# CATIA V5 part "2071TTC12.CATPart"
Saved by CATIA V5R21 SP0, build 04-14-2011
Part number: 2071TTC12
Bounding box of the stored display mesh (mm): x -10 to 10, y 0 to 1000, z -16 to 14
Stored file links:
  C:\Users\ALI OZGUN\Desktop\alhan\PROFILLER\2071TTC12.CATPart
  Copy (1) of 2070TT001.CATPart
  C:\Users\ALI OZGUN\Desktop\alhan\PROFILLER\2071TTC38.CATPart
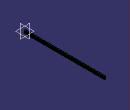
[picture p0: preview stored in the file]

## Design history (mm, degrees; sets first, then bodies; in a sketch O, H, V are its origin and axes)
Body1 (main body)
  Sketch1 on zx-plane, origin (0, 0, 0), H (-1, 0, 0), V (0, 0, 1)
    line L1 (10, 11.8) -> (10, -14)
    line L2 (10, -14) -> (-10, -14)
    line L3 (-10, -14) -> (-10, -1.7)
    line L4 (-10, 14) -> (-2.6, 14)
    point P4 (-10, 2.6)
    line L5 (-2.6, -1.7) -> (-10, -1.7)
    line L6 (-10, 6.9) -> (-2.6, 6.9)
    point P5 (-9.0936, 12.527)
    point P6 (-0.35, 2.6)
    line L7 (1.9, 9.1) -> (1.9, -3.9)
    line L8 (1.9, -3.9) -> (-2.6, -3.9)
    line L9 (-2.6, -3.9) -> (-2.6, -1.7)
    line L10 (-2.6, 9.1) -> (1.9, 9.1)
    line L11 (10, 11.8) -> (-2.6, 11.8)
    line L12 (-2.6, 11.8) -> (-2.6, 14)
    axis line L13 (-44.5224, 2.6) -> (23.1973, 2.6)
    line L14 (-10, 6.9) -> (-10, 14)
    point P18 (-2.6, 6.9)
    line L15 (-2.6, 6.9) -> (-2.6, 9.1)
    distance L6 L5 = 8.6
    distance L10 L8 = 13
    distance L7 L9 = 4.5
    distance L12 L3 = 7.4
    distance L1 L3 = 20
    distance L4 L2 = 28
    distance L11 L4 = 2.2
    distance L13 L4 = 11.4
    vertical: L1 V, L3 V, L7 V, L9 V, L12 V, L14 V, L15 V
    horizontal: L2 H, L4 H, L5 H, L6 H, L8 H, L10 H, L11 H, L13 H
    equidistance: L1 L3 O, L2 L4 O, L5 L6 P4, L7 L9 P6, L8 L10 P6
    coincidence: P4 L3, L9 L12, L3 L14, L9 P18, L9 L15
    symmetry: L6 L5 L13, L8 L10 L13
  Pad1: profile Sketch1, direction (0, 1, 0), length 1000
  Body2
    Solid1: linked copy from another document
  Remove1: tool Body2
  RemoveFace1: RemoveFaces (face of Solid1; face of Solid1)
Body3
Body4
  Sketch2, origin (0, 0, 0), H (1, 0, 0), V (0, 0, 1)
    point P1 (-5, -6)
    line L1 (-5, -6) -> (-9, -6)
    line L2 (-10, -7) -> (-10, -15)
    line L3 (-9, -16) -> (9, -16)
    line L4 (10, -15) -> (10, -7)
    point P2 (10, -6)
    line L5 (9, -6) -> (5, -6)
    point P3 (5, -6)
    arc A1 centre (-9, -7) radius 1 from (-9, -6) to (-10, -7) ccw
    arc A2 centre (-9, -15) radius 1 from (-10, -15) to (-9, -16) ccw
    arc A3 centre (9, -15) radius 1 from (9, -16) to (10, -15) ccw
    arc A4 centre (9, -7) radius 1 from (10, -7) to (9, -6) ccw
    reference projected line E1 (2.6, 14) -> (10, 14) from edge [start face of Pad1 | face of Pad1 from Sketch1.L4]
    distance L4 L2 = 20
    distance L3 L5 = 10
    radius A1 = 1
    radius A2 = 1 {= Sketch2.radius(A1)}
    radius A3 = 1 {= Sketch2.radius(A1)}
    radius A4 = 1 {= Sketch2.radius(A1)}
    distance P3 P1 = 10
    distance L3 E1 = 30
    horizontal: L1 H, L3 H, L5 H
    vertical: L2 V, L4 V
    coincidence: P2 L1
    symmetry: L5 L1 V, L4 L2 V, P3 P1 V
    tangency: A1 L1, A1 L2, A2 L2, A2 L3, A3 L3, A3 L4, A4 L4, A4 L5
  Pad2: profile Sketch2, direction (0, 1, 0), length 1000, thin wall 1.5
